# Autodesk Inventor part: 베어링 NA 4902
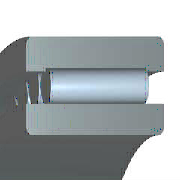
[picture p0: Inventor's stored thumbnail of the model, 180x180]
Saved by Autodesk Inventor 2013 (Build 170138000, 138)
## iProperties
IsCustomPart: 0
Manager: KYOUNG IL JANG
Company: 한국ATC센터
Created: 2009-02
Part Number: 베어링 NA 4902
Material: Steel, Mild
Description: 니들 롤러 베어링 - 경계 치수 및 공차
Document SubType Name: Modeling
Standard: KS B 2029
Standards Organization: KS
Language: ko-KR
Size Designation: NA 4902 - 15 x 28 x 13
Categories: <MemberInstance><Categories><Category DisplayName="샤프트 부품" InternalName="7f7aeb1f-a693-4053-b835-cee3144e0d98" Mnemonic="SHFT"><Category DisplayName="베어링" Inter
Density: 1 g/cm^3
Checked By: KYOUNG IL JANG
Vendor: CBT Solutions
Designer: KYOUNG IL JANG
Author: KYOUNG IL JANG
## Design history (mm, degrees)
sketch "스케치"
  geometry: L1 (1.857, 11.5)-(11.143, 11.5); L2 (11.143, 11.5)-(11.143, 10); L3 (13, 10)-(0, 10); L4 (1.857, 10)-(1.857, 11.5); L5 (1.857, 10.75)-(11.143, 10.75); L6 (6.5, 10.75)-(6.5, 10); L7 (0, 7.5)-(13, 7.5); L8 (0, 14)-(13, 14); L9 (13, 7.5)-(13, 10); L10 (13, 11.35)-(13, 14); L11 (1.857, 11.35)-(0, 11.35); L12 (11.143, 11.35)-(13, 11.35); L13 (-6, 0)-(36, 0) reference; L14 (0, -1.9)-(0, 14.9) reference
  constraints: 24 end point, 8 point on line, 3 midpoint, 3 parallel, 3 perpendicular, 2 symmetric about line, 1 horizontal, 1 other
  dimensions: "d6" = 15 diameter of L7 L13 (= WD); "d7" = 20 diameter of L3 L13 (= KID1); "d8" = 28 diameter of L8 L13 (= BD); "d9" = 21.5 diameter of L6.start L13 (= 0.5 x WD + 0.5 x BD); "d10" = 22.7 diameter of L12 L13 (= 0.9 x BD + 0.9 x WD - 0.8 x KID1); "d11" = 23 diameter of L1 L13 (= BD + WD - KID1); "d12" = 1.85714 distance between parallel lines of L14 L4 (= 0.142857 x KB); "d13" = 13 distance between parallel lines of L14 L9 (= KB); "d14" = 11.14286 distance between parallel lines of L14 L2 (= 0.857143 x KB)
revolve "본체" stored, may be unused: angle "d17" = 90 deg
revolve "롤러" stored, may be unused: angle "d18" = 90 deg
body "Solid1"
fillet "모깎기1" dims "d0" = 0.3 (= KRS)
pattern_circular "IDS_ARRAYROLLER[SIMPL:T]" dims angle "d2" = 360 deg
other parameters: "WD" = 15 [user parameter; used in 6 equation terms], "BD" = 28 [user parameter; used in 6 equation terms], "KB" = 13 [user parameter; used in 3 equation terms], "KID1" = 20 [user parameter; used in 4 equation terms], "KRS" = 0.3 [user parameter; used in 1 equation term], "d3" = 0, "d4" = 0, "d5" = 0, "d15" = 0, "d16" = 0, "BC0" = 1.37e+07 [user parameter], "WR" = 7.5 (= 0.5 x WD) [user parameter], "BBA" = 0 [user parameter], "BC" = 1.02e+07 [user parameter], "BR" = 14 (= 0.5 x BD) [user parameter]
